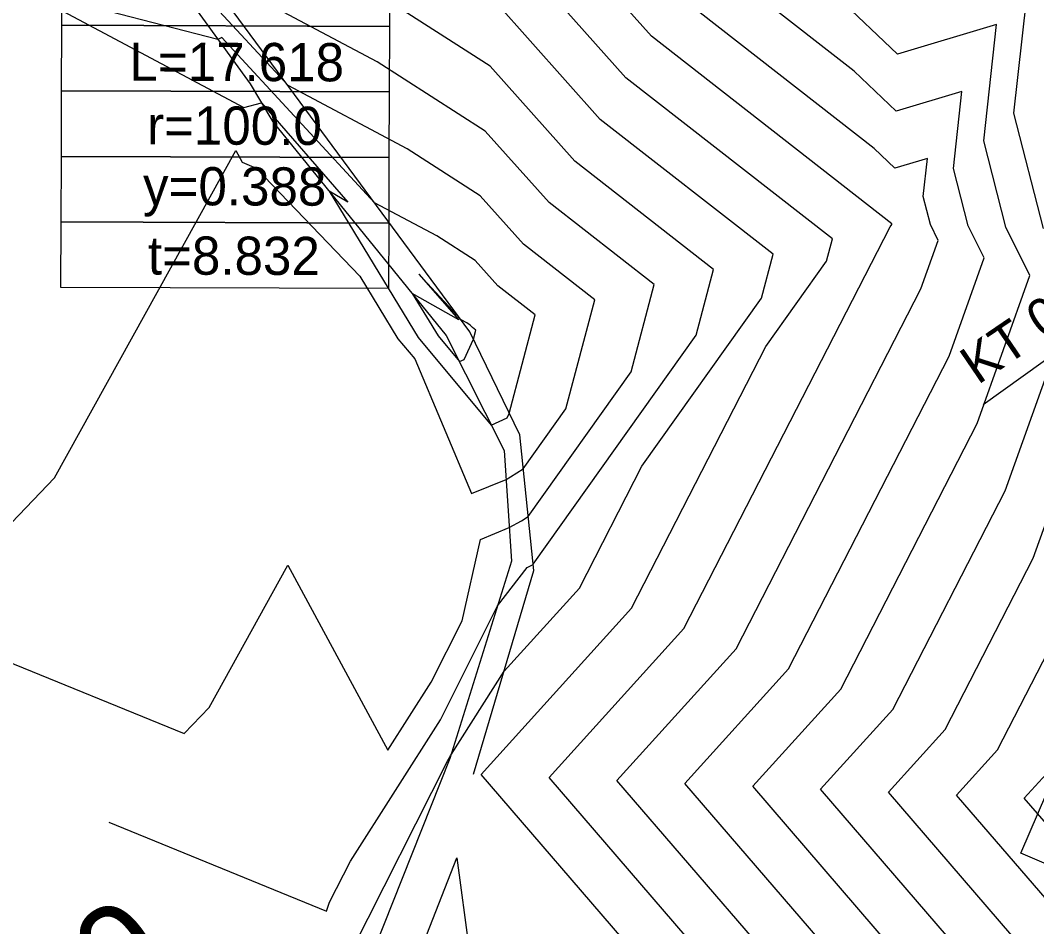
# Model space of a CAD drawing. Extents: x -549394 to -546608, y -1037055 to -1033629.
# Drawn here: x -548286 to -548193, y -1035675.8 to -1035592.8 of the extents above; entities that cross this region are included whole.
import ezdxf

# ---------------------------------------------------------------- set-up
doc = ezdxf.new("R2010")
doc.units = 0
for name, color, linetype in [('hlavni_vrst', 7, 'Continuous'), ('hrana_L', 7, 'Continuous'), ('norm_vrst', 7, 'Continuous'), ('x_popis_oblouky_C11', 7, 'Continuous'), ('x_popis_pricne_rezy_C11', 7, 'Continuous')]:
    doc.layers.add(name, color=color, linetype=linetype)

msp = doc.modelspace()

# ---------------------------------------------------------------- linework, layer by layer
at = {"layer": 'hlavni_vrst'}
for p, q in [((-548209.69, -1035597.452), (-548223.569, -1035586.629)), ((-548243.032, -1035597.002), (-548256.095, -1035588.612)), ((-548235.284, -1035605.679), (-548243.032, -1035597.002)), ((-548205.838, -1035601.107), (-548209.69, -1035597.452)), ((-548199.822, -1035599.315), (-548205.838, -1035601.107)), ((-548200.609, -1035606.37), (-548199.822, -1035599.315)), ((-548222.567, -1035615.596), (-548235.284, -1035605.679)), ((-548199.264, -1035611.61), (-548200.609, -1035606.37)), ((-548197.801, -1035614.545), (-548199.264, -1035611.61)), ((-548201.01, -1035623.537), (-548197.801, -1035614.545)), ((-548224.15, -1035621.61), (-548222.567, -1035615.596)), ((-548239.08, -1035642.592), (-548224.15, -1035621.61)), ((-548215.712, -1035652.176), (-548201.01, -1035623.537)), ((-548239.64, -1035642.9), (-548239.15, -1035642.637)), ((-548239.15, -1035642.637), (-548239.08, -1035642.592)), ((-548242.356, -1035646.409), (-548239.64, -1035642.9)), ((-548247.58, -1035656.85), (-548242.356, -1035646.409)), ((-548225.203, -1035662.653), (-548215.712, -1035652.176)), ((-548255.82, -1035669.78), (-548247.58, -1035656.85)), ((-548194.115, -1035664.008), (-548191.781, -1035661.432)), ((-548200.805, -1035690.941), (-548225.203, -1035662.653)), ((-548188.117, -1035670.963), (-548194.115, -1035664.008)), ((-548277.956, -1035666.216), (-548258.012, -1035674.357)), ((-548257.725, -1035673.541), (-548255.82, -1035669.78)), ((-548258.012, -1035674.357), (-548257.725, -1035673.541))]:
    msp.add_line(p, q, dxfattribs=at)
at = {"layer": 'hrana_L'}
for p, q in [((-548244.89, -1035621.3), (-548280.93, -1035572.5)), ((-548282.38, -1035574.67), (-548265, -1035598.62)), ((-548265, -1035598.62), (-548262.94, -1035602.09)), ((-548262.94, -1035602.09), (-548247.04, -1035621.64)), ((-548247.04, -1035621.64), (-548241.75, -1035632.18)), ((-548240.32, -1035630.76), (-548244.89, -1035621.3)), ((-548239.02, -1035643.16), (-548240.32, -1035630.76)), ((-548241.75, -1035632.18), (-548241.07, -1035642.3)), ((-548241.07, -1035642.3), (-548246.73, -1035660.38)), ((-548244.54, -1035661.81), (-548239.02, -1035643.16)), ((-548246.73, -1035660.38), (-548256.67, -1035685.46))]:
    msp.add_line(p, q, dxfattribs=at)
at = {"layer": 'norm_vrst'}
for p, q in [((-548228.255, -1035594.249), (-548241.673, -1035579.223)), ((-548230.598, -1035598.059), (-548242.126, -1035585.149)), ((-548261.524, -1035598.777), (-548271.457, -1035588.033)), ((-548253.362, -1035596.585), (-548269.445, -1035588.052)), ((-548286.044, -1035589.872), (-548265.573, -1035600.78)), ((-548267.955, -1035594.547), (-548286.044, -1035589.872)), ((-548207.852, -1035604.522), (-548225.912, -1035590.439)), ((-548205.72, -1035595.892), (-548211.527, -1035590.382)), ((-548232.941, -1035601.869), (-548242.579, -1035591.076)), ((-548195.064, -1035601.284), (-548193.912, -1035590.947)), ((-548196.65, -1035593.191), (-548205.72, -1035595.892)), ((-548197.836, -1035603.827), (-548196.65, -1035593.191)), ((-548206.233, -1035611.422), (-548228.255, -1035594.249)), ((-548267.591, -1035594.372), (-548267.955, -1035594.547)), ((-548253.603, -1035609.502), (-548267.591, -1035594.372)), ((-548243.485, -1035602.928), (-548253.362, -1035596.585)), ((-548250.629, -1035604.557), (-548261.524, -1035598.777)), ((-548211.678, -1035612.813), (-548230.598, -1035598.059)), ((-548265.573, -1035600.78), (-548263.978, -1035600.342)), ((-548263.978, -1035600.342), (-548256.044, -1035609.429)), ((-548192.355, -1035611.843), (-548195.064, -1035601.284)), ((-548217.123, -1035614.204), (-548232.941, -1035601.869)), ((-548237.627, -1035609.489), (-548243.485, -1035602.928)), ((-548195.809, -1035611.727), (-548197.836, -1035603.827)), ((-548282.925, -1035634.695), (-548266.315, -1035604.699)), ((-548266.315, -1035604.699), (-548265.734, -1035605.775)), ((-548243.938, -1035608.855), (-548250.629, -1035604.557)), ((-548205.956, -1035606.321), (-548207.852, -1035604.522)), ((-548202.994, -1035605.439), (-548205.956, -1035606.321)), ((-548203.381, -1035608.913), (-548202.994, -1035605.439)), ((-548265.734, -1035605.775), (-548264.45, -1035606.344)), ((-548264.45, -1035606.344), (-548254.954, -1035616.227)), ((-548256.044, -1035609.429), (-548257.767, -1035608.451)), ((-548257.767, -1035608.451), (-548249.632, -1035621.823)), ((-548239.97, -1035613.299), (-548243.938, -1035608.855)), ((-548202.719, -1035611.493), (-548203.381, -1035608.913)), ((-548247.896, -1035612.53), (-548253.603, -1035609.502)), ((-548228.012, -1035616.987), (-548237.627, -1035609.489)), ((-548225.284, -1035648.473), (-548206.411, -1035611.709)), ((-548206.411, -1035611.709), (-548206.249, -1035611.481)), ((-548206.249, -1035611.481), (-548206.233, -1035611.422)), ((-548201.999, -1035612.939), (-548202.719, -1035611.493)), ((-548193.604, -1035616.152), (-548195.809, -1035611.727)), ((-548244.392, -1035614.781), (-548247.896, -1035612.53)), ((-548212.216, -1035614.858), (-548211.678, -1035612.813)), ((-548233.456, -1035618.378), (-548239.97, -1035613.299)), ((-548203.578, -1035617.366), (-548201.999, -1035612.939)), ((-548218.183, -1035618.234), (-548217.123, -1035614.204)), ((-548242.313, -1035617.109), (-548244.392, -1035614.781)), ((-548217.773, -1035622.667), (-548212.216, -1035614.858)), ((-548254.954, -1035616.227), (-548251.471, -1035621.953)), ((-548245.682, -1035620.227), (-548249.567, -1035616.026)), ((-548249.567, -1035616.026), (-548245.904, -1035620.221)), ((-548198.441, -1035629.708), (-548193.604, -1035616.152)), ((-548238.901, -1035619.77), (-548242.313, -1035617.109)), ((-548230.117, -1035624.987), (-548228.012, -1035616.987)), ((-548220.498, -1035650.325), (-548203.578, -1035617.366)), ((-548245.904, -1035620.221), (-548250.159, -1035617.805)), ((-548250.159, -1035617.805), (-548247.794, -1035621.693)), ((-548236.084, -1035628.363), (-548233.456, -1035618.378)), ((-548229.135, -1035633.626), (-548218.183, -1035618.234)), ((-548195.873, -1035635.879), (-548189.407, -1035617.759)), ((-548193.304, -1035642.05), (-548185.21, -1035619.365)), ((-548245.163, -1035620.503), (-548245.682, -1035620.227)), ((-548241.273, -1035628.786), (-548238.901, -1035619.77)), ((-548244.845, -1035620.707), (-548245.163, -1035620.503)), ((-548244.656, -1035620.919), (-548244.845, -1035620.707)), ((-548244.346, -1035621.161), (-548244.656, -1035620.919)), ((-548244.561, -1035621.981), (-548244.346, -1035621.161)), ((-548251.471, -1035621.953), (-548249.936, -1035623.788)), ((-548249.632, -1035621.823), (-548242.919, -1035629.851)), ((-548247.794, -1035621.693), (-548245.842, -1035624.028)), ((-548245.419, -1035623.84), (-548244.561, -1035621.981)), ((-548230.07, -1035646.622), (-548217.773, -1035622.667)), ((-548249.936, -1035623.788), (-548244.725, -1035636.13)), ((-548245.842, -1035624.028), (-548245.419, -1035623.84)), ((-548239.537, -1035638.226), (-548230.117, -1035624.987)), ((-548239.995, -1035633.86), (-548236.084, -1035628.363)), ((-548242.919, -1035629.851), (-548241.466, -1035629.204)), ((-548241.466, -1035629.204), (-548241.273, -1035628.786)), ((-548210.926, -1035654.027), (-548198.441, -1035629.708)), ((-548241.15, -1035634.593), (-548239.995, -1035633.86)), ((-548234.856, -1035644.771), (-548229.135, -1035633.626)), ((-548288.178, -1035640.173), (-548282.925, -1035634.695)), ((-548244.725, -1035636.13), (-548241.573, -1035634.82)), ((-548241.573, -1035634.82), (-548241.15, -1035634.593)), ((-548206.14, -1035655.878), (-548195.873, -1035635.879)), ((-548241.277, -1035639.22), (-548240.15, -1035638.615)), ((-548240.15, -1035638.615), (-548239.537, -1035638.226)), ((-548243.912, -1035640.315), (-548241.277, -1035639.22)), ((-548245.597, -1035647.76), (-548243.912, -1035640.315)), ((-548268.769, -1035655.715), (-548261.544, -1035642.666)), ((-548261.544, -1035642.666), (-548252.389, -1035659.629)), ((-548201.353, -1035657.73), (-548193.304, -1035642.05)), ((-548241.749, -1035652.379), (-548234.856, -1035644.771)), ((-548243.856, -1035661.84), (-548230.07, -1035646.622)), ((-548248.413, -1035653.39), (-548245.597, -1035647.76)), ((-548196.567, -1035659.581), (-548190.735, -1035648.22)), ((-548237.638, -1035662.111), (-548225.284, -1035648.473)), ((-548290.043, -1035650.346), (-548271.055, -1035658.098)), ((-548231.421, -1035662.382), (-548220.498, -1035650.325)), ((-548246.557, -1035659.993), (-548241.749, -1035652.379)), ((-548252.389, -1035659.629), (-548248.413, -1035653.39)), ((-548218.985, -1035662.924), (-548210.926, -1035654.027)), ((-548271.055, -1035658.098), (-548268.769, -1035655.715)), ((-548212.768, -1035663.195), (-548206.14, -1035655.878)), ((-548206.55, -1035663.466), (-548201.353, -1035657.73)), ((-548246.908, -1035660.564), (-548246.747, -1035660.311)), ((-548246.747, -1035660.311), (-548246.644, -1035660.106)), ((-548246.644, -1035660.106), (-548246.557, -1035659.993)), ((-548200.332, -1035663.737), (-548196.567, -1035659.581)), ((-548257.093, -1035680.678), (-548246.908, -1035660.564)), ((-548208.419, -1035702.927), (-548243.856, -1035661.84)), ((-548205.881, -1035698.932), (-548237.638, -1035662.111)), ((-548203.343, -1035694.936), (-548231.421, -1035662.382)), ((-548198.268, -1035686.945), (-548218.985, -1035662.924)), ((-548195.73, -1035682.949), (-548212.768, -1035663.195)), ((-548193.192, -1035678.954), (-548206.55, -1035663.466)), ((-548190.654, -1035674.958), (-548200.332, -1035663.737)), ((-548254.016, -1035689.798), (-548246.08, -1035669.468)), ((-548246.08, -1035669.468), (-548241.977, -1035699.748))]:
    msp.add_line(p, q, dxfattribs=at)
at = {"layer": 'x_popis_oblouky_C11'}
for points in [[(-548282.226, -1035587.248), (-548252.226, -1035587.353), (-548252.247, -1035593.353), (-548282.247, -1035593.248)], [(-548282.247, -1035593.248), (-548252.247, -1035593.353), (-548252.268, -1035599.353), (-548282.268, -1035599.248)], [(-548282.268, -1035599.248), (-548252.268, -1035599.353), (-548252.289, -1035605.353), (-548282.289, -1035605.248)], [(-548282.289, -1035605.248), (-548252.289, -1035605.353), (-548252.31, -1035611.353), (-548282.31, -1035611.248)], [(-548282.31, -1035611.248), (-548252.31, -1035611.353), (-548252.331, -1035617.353), (-548282.33, -1035617.248)], [(-548166.843, -1035680.844), (-548194.421, -1035669.034), (-548192.059, -1035663.519), (-548164.481, -1035675.329)]]:
    msp.add_lwpolyline(points, close=True, dxfattribs=at)
msp.add_lwpolyline([(-548164.27, -1035603.906), (-548197.897, -1035628.009)], dxfattribs=at)

# ---------------------------------------------------------------- texts
for s, rotation, p in [('L=17.618', 359.82224, (-548276.059, -1035598.325)), ('r=100.0', 359.82224, (-548274.446, -1035604.159)), ('y=0.388', 359.82224, (-548274.816, -1035609.716)), ('KT 0.59695', 34.25792, (-548198.378, -1035626.219)), ('t=8.832', 359.82224, (-548274.372, -1035616.07))]:
    msp.add_text(s, height=3.5, rotation=rotation, dxfattribs=at).set_placement(p)
at = {"layer": 'x_popis_pricne_rezy_C11'}
msp.add_text('PŘ 7 km 0.6000', height=9.06272, rotation=32.81205, dxfattribs=at).set_placement((-548344.604, -1035727.327))

doc.saveas('drawing.dxf')
